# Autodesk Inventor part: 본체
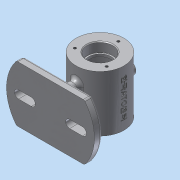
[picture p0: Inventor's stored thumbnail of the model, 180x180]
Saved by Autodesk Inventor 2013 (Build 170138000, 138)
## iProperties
Created: 2017-12
Part Number: 본체
Material: 알루미늄 6061
Document SubType Name: Modeling
Designer: Administrator
Density: 2.71 g/cm^3
Mass: 467.681 g
Surface Area: 486.49 cm^2
Volume: 172.576 cm^3
Author: Administrator
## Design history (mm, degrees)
sketch "스케치1"
  geometry: C1 r 30 at (0, 0); 1 further point
  constraints: 1 centre point, 1 coincident
  dimensions: "d0" = 60 diameter of C1
extrude "돌출1" new body sketch "스케치1" stored distance "d2" = 70; taper "d3" = 0 deg
sketch "스케치2"
  geometry: L1 (30, -35)-(-30, -35) reference; L2 (-30, -35)-(-30, 35) reference; L3 (-30, 35)-(30, 35) reference; L4 (30, 35)-(30, -35) reference; L5 (0, 35)-(0, 0); L6 (16, 35)-(16, 23); L7 (16, 23)-(14, 23); L8 (14, 23)-(14, 20); L9 (14, 20)-(25, 20); L10 (25, 20)-(25, 0); L11 (25, 0)-(0, 0); L12 (16, 35)-(-0.423, 35)
  constraints: 16 end point, 5 parallel, 3 point on line, 1 midpoint, 1 perpendicular
  dimensions: "d4" = 50 diameter of L10 L5; "d6" = 32 diameter of L6 L5; "d7" = 28 diameter of L8 L5; "d8" = 12 distance between parallel lines of L7 L3; "d9" = 3 distance between parallel lines of L9 L7
revolve "회전1" sketch "스케치2" stored, may be unused: angle "d10" = 90 deg
sketch "스케치4"
  geometry: L1 (0, 0)-(-33.046, -19.079); L2 (0, 0)-(33.646, -19.426); L3 (0, 0)-(0, 23); C1 r 16 at (0, 0) reference; C2 r 30 at (0, 0) reference; A1 r 23 centre (0, 0) between (0, 23) and (-19.919, -11.5); 1 further point
  constraints: 6 end point, 3 point on circle, 2 point on line, 1 centre point, 1 coincident, 1 vertical, 1 vertical alignment
  dimensions: "d11" = 46 diameter of A1; "d13" = 120 deg angle of L2 L3; "d15" = 120 deg angle of L3 L1
hole "구멍1" sketch "스케치4" at (0, 23), (-19.919, -11.5), (19.919, -11.5) diameter "d17" = 3.242; stored, may be unused: countersink angle "d21" = 90 deg, drill point angle "d23" = 118 deg; dims "d18" = 8, "d19" = 4, "d20" = 2, "d22" = 10
fillet "모깎기1" dims "d24" = 3
chamfer "모따기1" distance "d25" = 1; stored, may be unused: second distance "d26" = 2, angle "d27" = 45 deg
fillet "모깎기2" dims "d28" = 0.3
node "작업 평면2"
sketch "스케치6"
  geometry: C1 r 8 at (0, 0); 1 further point
  constraints: 1 centre point, 1 coincident
  dimensions: "d30" = 16 diameter of C1
extrude "돌출2" join sketch "스케치6" stored distance "d32" = 70; taper "d33" = 0 deg
sketch "스케치8"
  geometry: C1 r 8 at (0, 0) reference; C2 r 4 at (0, 0)
  constraints: 1 centre point, 1 coincident
  dimensions: "d34" = 8 diameter of C2
extrude "돌출3" cut sketch "스케치8" distance "d36" = 30; taper "d37" = 0 deg
chamfer "모따기2" distance "d38" = 1; stored, may be unused: second distance "d39" = 2, angle "d40" = 45 deg
fillet "모깎기3" dims "d41" = 3
sketch "스케치9"
  geometry: 1 further point
node "작업 평면3"
sketch "스케치10"
  geometry: L1 (-42.426, 35)-(42.426, 35); L2 (-42.426, -35)-(42.426, -35); A1 r 55 centre (0, 0) between (-42.426, 35) and (-42.426, -35); A2 r 55 centre (0, 0) between (42.426, -35) and (42.426, 35); 1 further point
  constraints: 4 end point, 4 point on circle, 2 centre point, 1 coincident, 1 horizontal, 1 parallel
  dimensions: "d47" = 35 vertical distance of L1.end point (0, 0); "d48" = 35 vertical distance of L2.end point (0, 0); "d49" = 55 radius of A1; "d50" = 55 radius of A2
extrude "돌출4" join sketch "스케치10" distance "d51" = 10; taper "d52" = 0 deg
sketch "스케치11"
  geometry: L1 (42.426, 35)-(-42.426, 35) reference; L2 (-40, -5)-(-24, -5); L3 (-40, 5)-(-24, 5); L4 (-42.426, 35)-(42.426, 35) reference; L5 (42.426, -35)-(-42.426, -35) reference; A1 r 55 centre (0, 0) between (42.426, -35) and (42.426, 35) reference; A2 r 5 centre (-40, 0) between (-40, 5) and (-40, -5); A3 r 5 centre (-24, 0) between (-24, -5) and (-24, 5); A4 r 55 centre (0, 0) between (-42.426, 35) and (-42.426, -35) reference; A5 r 55 centre (0, 0) between (42.426, -35) and (42.426, 35) reference
  constraints: 4 end point, 4 point on circle, 4 tangent, 2 centre point, 2 parallel, 1 horizontal alignment
  dimensions: "d53" = 5 radius of A2; "d56" = 16 distance of A3.centre A2.centre; "d57" = 24 distance of A1.centre A3.centre
extrude "돌출5" cut sketch "스케치11" distance "d58" = 10; taper "d59" = 0 deg
fillet "모깎기4" dims "d60" = 3
sketch "스케치12"
  geometry: L1 (-40, 5)-(-24, 5) reference; L2 (-5, 15)-(-5, -15); L3 (5, -15)-(5, 15); A1 r 55 centre (0, 0) between (43.352, -33.846) and (43.352, 33.846) reference; A2 r 5 centre (0, -15) between (-5, -15) and (5, -15); A3 r 5 centre (0, 15) between (5, 15) and (-5, 15)
  constraints: 4 end point, 4 point on circle, 4 tangent, 2 centre point, 1 parallel, 1 perpendicular, 1 vertical alignment
  dimensions: "d61" = 30 distance of A3.centre A2.centre; "d63" = 5 radius of A2; "d64" = 15 distance of A3.centre A1.centre
extrude "돌출6" join sketch "스케치12" stored distance "d65" = 10; taper "d66" = 0 deg
fillet "모깎기5" dims "d67" = 5
node "작업 평면5"
sketch "스케치13"
  geometry: L1 (30, 35)-(-30, 35) reference; L2 (30, -35)-(30, 35) reference; 2 further points
  constraints: 1 other
  dimensions: "d69" = 35 distance from line of L1 point (0, 0); "d70" = 30 distance from line of L2 point (0, 0)
feature "엠보싱1" sketch "스케치13" dims "d71" = 0.5, "d72" = 0
node "솔리드1"
mirror "대칭1"
mirror "대칭2"
mirror "대칭3"
node "작업 평면1"
node "작업 평면4"
node "절단 모서리 투영1"
node "절단 모서리 투영2"
other parameters: "d29" = 37, "d42" = -62, "d68" = 83.75
